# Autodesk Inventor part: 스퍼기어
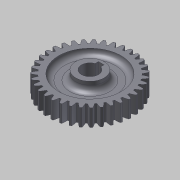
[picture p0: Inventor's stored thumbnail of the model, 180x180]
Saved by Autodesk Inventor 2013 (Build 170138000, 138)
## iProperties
Created: 2013-08
Part Number: 스퍼기어
Material: 강
Document SubType Name: Modeling
Designer: 한국산업디자인학원
Categories: <?xml version="1.0" encoding="UTF-16"?> <MemberInstance><Categories><FamilyTemplate><FamilyTemplateParameter ValueType="xs:double" Id="1" ObjectReferenceKey="da
Density: 1 g/cm^3
CustomPartVersion: 1
Author: 한국산업디자인학원
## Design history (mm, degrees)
sketch "Sketch1"
  geometry: C1 r 37 at (0, 0)
  constraints: 1 centre point
  dimensions: "d0" = 74 diameter of C1 (= da_da)
extrude "Extrusion1" new body sketch "Sketch1" distance "d1" = 15 (= da_b); taper "d2" = 0 deg
workplane "Work Plane2"
feature "피치 지름" dims "d4" = 10, "d5" = 0
workplane "Work Plane8"
workplane "Work Plane9"
feature "스퍼 기어" dims "da_b" = 15, "da_d" = 70, "da_aw" = 70, "da_da" = 74, "da_df" = 65, "da_dw" = 70, angle "da_beta" = 0 deg, "da_lefttooth" = 0, "da_righttooth" = 0
sketch "스케치4"
  geometry: C1 r 12.5 at (0, 0); A1 r 37 centre (0, 0) between (-5.788, 36.544) and (-7.422, 36.248) reference
  constraints: 1 centre point, 1 coincident
  dimensions: "d49" = 25 diameter of C1
extrude "돌출2" join sketch "스케치4" distance "d51" = 3; taper "d52" = 0 deg
sketch "스케치5"
  geometry: C1 r 12.5 at (0, 0); A1 r 32.5 centre (0, 0) between (9.347, 31.127) and (7.941, 31.515) reference
  constraints: 1 centre point, 1 coincident
  dimensions: "d53" = 25 diameter of C1
extrude "돌출3" join sketch "스케치5" distance "d55" = 13; taper "d56" = 0 deg
sketch "스케치6"
  geometry: L1 (0, 32.899)-(0, -32.899); L2 (12.5, 18)-(-12.5, 18) reference; L3 (12.5, 15)-(12.5, 18) reference; L4 (15.302, 15)-(12.1, 15) reference; L5 (26.163, 15)-(21.927, 15) reference; L6 (36.991, 15)-(36.991, 0) reference; L7 (17.291, 0)-(21.071, 0) reference; L8 (-12.5, -13)-(12.5, -13) reference; L9 (12.5, 0)-(12.5, -13) reference; L10 (27.5, 10)-(12.5, 10); L11 (12.5, 0)-(27.5, 0); L12 (27.5, 0)-(27.5, 5); L13 (27.5, 5)-(12.5, 5); L14 (12.5, 5)-(12.5, 0); L15 (27.5, 10)-(27.5, 18); L16 (27.5, 18)-(12.5, 18); L17 (12.5, 18)-(12.5, 10); 3 further points
  constraints: 18 end point, 3 parallel, 2 horizontal, 2 perpendicular, 2 vertical, 1 coincident, 1 midpoint, 1 point on line
  dimensions: "d61" = 55 diameter of L15 L1; "d62" = 55 diameter of L12 L1; "d63" = 8 distance of L2.start L10.end; "d64" = 5 distance of L11.end L12.end
revolve "회전1" sketch "스케치6" stored, may be unused: angle "d65" = 90 deg
sketch "스케치7" dims "d66" = 15
  geometry: L1 (-2.5, 10)-(2.5, 10); L2 (2.5, 10)-(2.5, 7.071); L3 (2.5, 7.071)-(-2.5, 7.071); L4 (-2.5, 7.071)-(-2.5, 10); C1 r 12.5 at (0, 0) reference; 2 further points
  constraints: 8 end point, 2 parallel, 1 coincident, 1 horizontal, 1 midpoint, 1 perpendicular, 1 vertical alignment, 3 other
  dimensions: "d68" = 5 distance of L1.start L1.end; "d69" = 10 distance of point (0, 0) point (0, 10)
extrude "돌출4" cut sketch "스케치7" distance "d70" = 54.5; taper "d71" = 0 deg
fillet "모깎기1" dims "d72" = 5
body "Solid1"
sketch "Sketch2"
  geometry: C1 r 37 at (0, 0) reference; C2 r 35 at (0, 0)
  constraints: 1 centre point, 1 coincident
  dimensions: "d3" = 70 diameter of C2 (= da_dw)
body "Srf1"
other parameters: "d17" = 0, "d34" = 0.8976 (computed from da_z), "d39" = 0, "d41" = 0, "d47" = 0, "d48" = 0
